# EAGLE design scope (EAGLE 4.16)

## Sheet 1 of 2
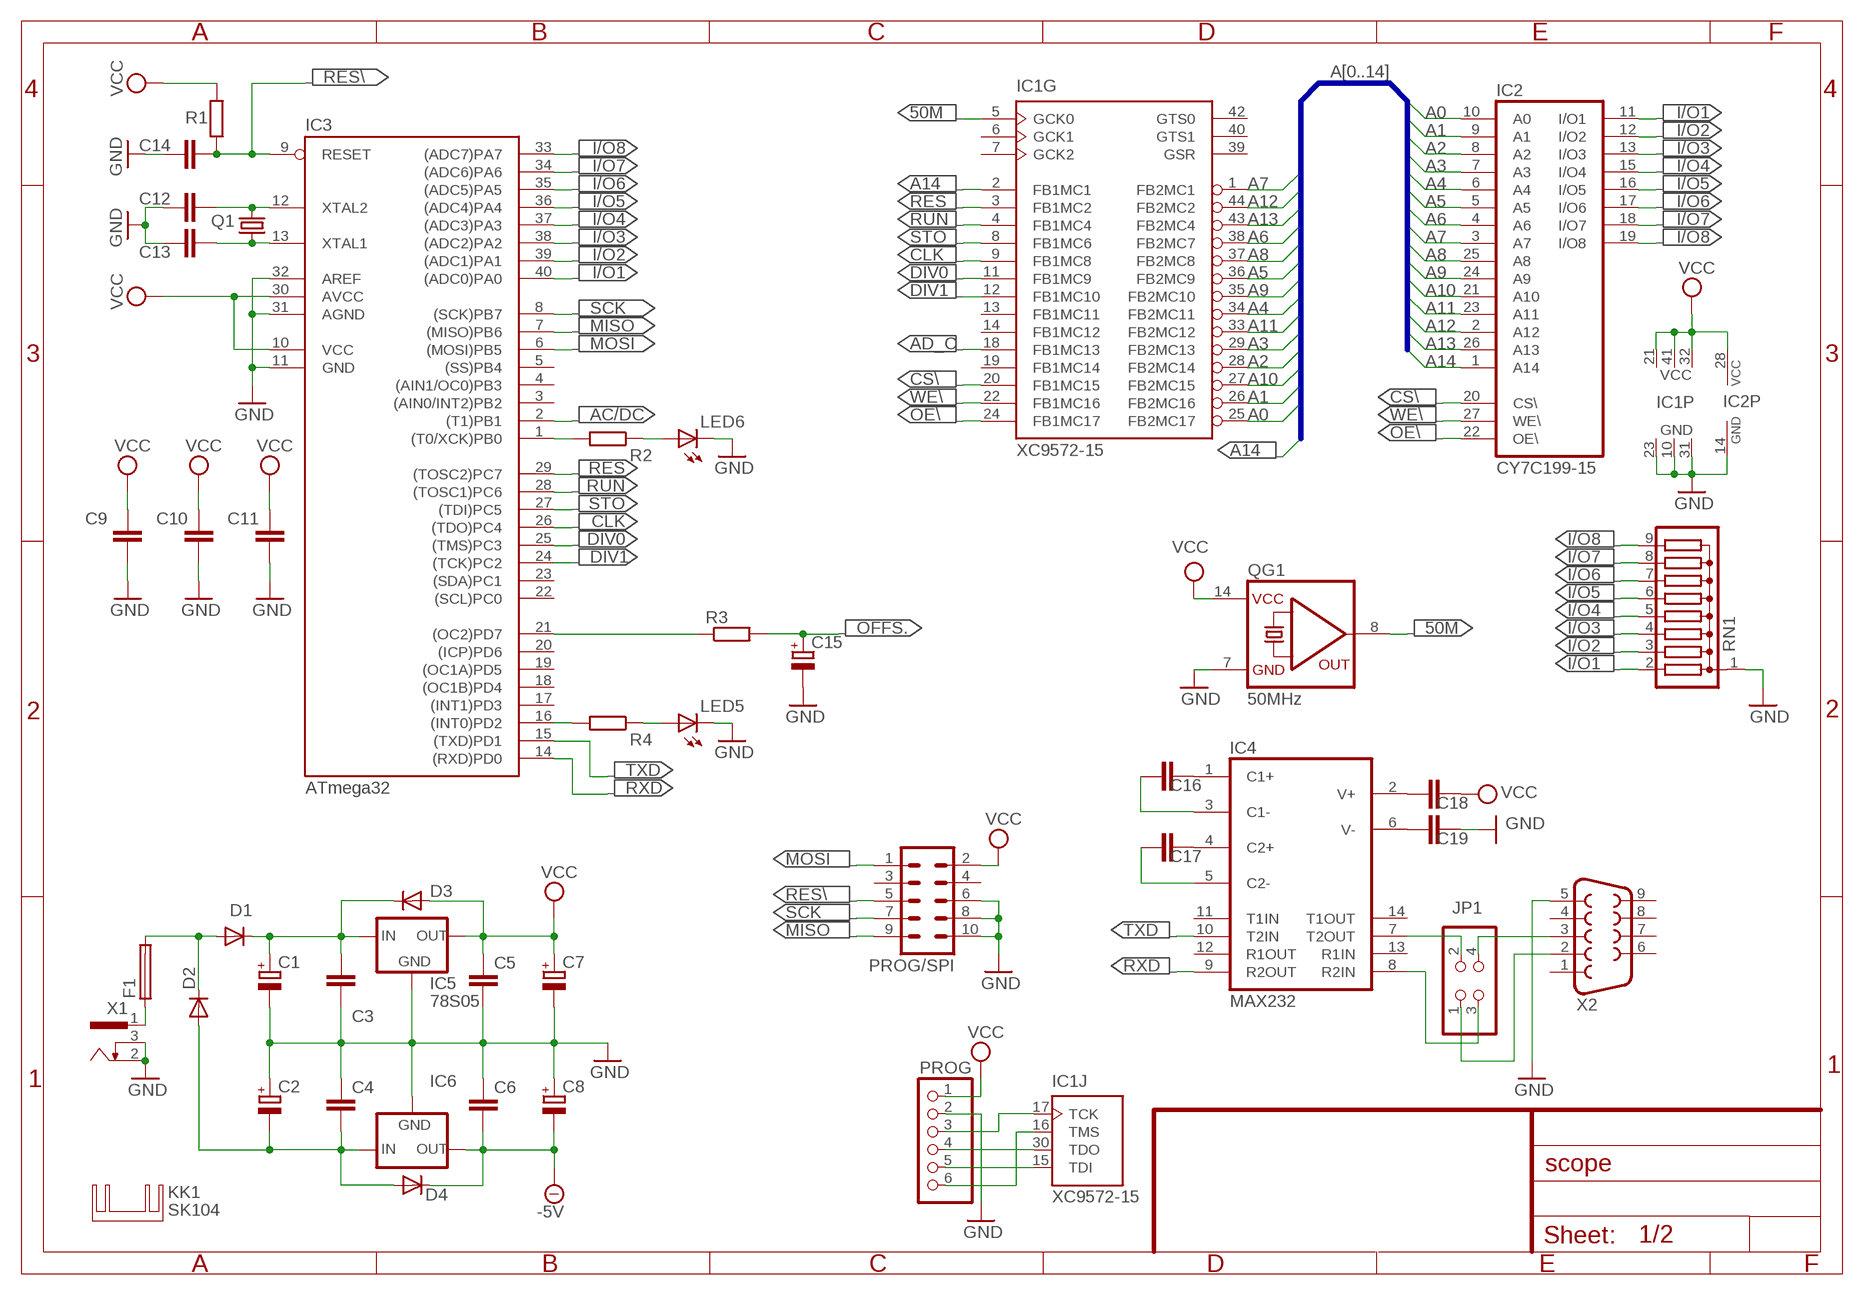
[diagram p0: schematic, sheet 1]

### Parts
C1  CPOL-EUE5-13  [E5-13]
C2  CPOL-EUE5-10.5  [E5-10,5]
C3  C-EU050-024X044  [C050-024X044]
C4  C-EU050-024X044  [C050-024X044]
C5  C-EU050-024X044  [C050-024X044]
C6  C-EU050-024X044  [C050-024X044]
C7  CPOL-EUE3.5-8  [E3,5-8]
C8  CPOL-EUE3.5-8  [E3,5-8]
C9  C-EU025-025X050  [C025-025X050]
C10  C-EU025-025X050  [C025-025X050]
C11  C-EU025-025X050  [C025-025X050]
C12  C-EU025-025X050  [C025-025X050]
C13  C-EU025-025X050  [C025-025X050]
C14  C-EU025-025X050  [C025-025X050]
C15  CPOL-EUE2-5  [E2-5]
C16  C-EU050-024X044  [C050-024X044]
C17  C-EU050-024X044  [C050-024X044]
C18  C-EU050-024X044  [C050-024X044]
C19  C-EU050-024X044  [C050-024X044]
D1  1N4004  [DO41-10]
D2  1N4004  [DO41-10]
D3  1N4004  [DO41-10]
D4  1N4004  [DO41-10]
F1  PICOFUSE  [PICOFUSE]
IC1  XC9572-15  XC9536-44  [PLCC-S44]
IC2  CY7C199-15  MB84256PSK  [DIL28-3]
IC3  ATmega32  MEGA32-P  [DIL40]
IC4  MAX232  [DIL16]
IC5  78S05  78XXS  [78XXS]
IC6  79XXS  [79XXS]
JP1  PINHD-2X2  [2X02]
KK1  SK104  [SK104]
LED5  LED3MM  [LED3MM]
LED6  LED3MM  [LED3MM]
PROG  PINHD-1X6  [1X06]
PROG/SPI  ML10  [ML10]
Q1  CRYSTALHC49U-V  [HC49U-V]
QG1  50MHz  QG5860  [DIL14S]
R1  R-EU_0207/10  [0207/10]
R2  R-EU_0207/10  [0207/10]
R3  R-EU_0207/10  [0207/10]
R4  R-EU_0207/10  [0207/10]
RN1  G08R  [SIL9]
X1  SCD-014A  [SCD-014-A]
X2  F09HP  [F09HP]

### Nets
50M: IC1.5(G:GCK0) QG1.8(OUT)
-5V: C6.2 C8.- D4.C IC6.OUT ; also sheet 2
A0: IC1.25(G:FB2MC17) IC2.10(A0)
A1: IC1.26(G:FB2MC16) IC2.9(A1)
A2: IC1.28(G:FB2MC14) IC2.8(A2)
A3: IC1.29(G:FB2MC13) IC2.7(A3)
A4: IC1.34(G:FB2MC11) IC2.6(A4)
A5: IC1.36(G:FB2MC9) IC2.5(A5)
A6: IC1.38(G:FB2MC7) IC2.4(A6)
A7: IC1.1(G:FB2MC1) IC2.3(A7)
A8: IC1.37(G:FB2MC8) IC2.25(A8)
A9: IC1.35(G:FB2MC10) IC2.24(A9)
A10: IC1.27(G:FB2MC15) IC2.21(A10)
A11: IC1.33(G:FB2MC12) IC2.23(A11)
A12: IC1.44(G:FB2MC2) IC2.2(A12)
A13: IC1.43(G:FB2MC4) IC2.26(A13)
A14: IC1.2(G:FB1MC1) IC2.1(A14)
AC/DC: IC3.2((T1)PB1) ; also sheet 2
AD_C: IC1.18(G:FB1MC13) ; also sheet 2
CLK: IC1.9(G:FB1MC8) IC3.26((TDO)PC4)
CS\: IC1.20(G:FB1MC15) IC2.20(CS\)
DIV0: IC1.11(G:FB1MC9) IC3.25((TMS)PC3)
DIV1: IC1.12(G:FB1MC10) IC3.24((TCK)PC2)
GND: C1.- C2.+ C3.2 C4.1 C5.2 C6.1 C7.- C8.+ C9.1 C10.1 C11.1 C12.1 C13.1 C14.1 C15.- C19.2 IC1.10(P:GND) IC1.23(P:GND) IC1.31(P:GND) IC2.14(GND) IC3.11(GND) IC3.31(AGND) IC3.32(AREF) IC5.GND IC6.GND LED5.K(C) LED6.K(C) PROG.2 PROG/SPI.6 PROG/SPI.8 PROG/SPI.10 QG1.7(GND) RN1.1 X1.2 X1.3 X2.5 ; also sheet 2
I/O1: IC2.11(I/O1) IC3.40((ADC0)PA0) RN1.2 ; also sheet 2
I/O2: IC2.12(I/O2) IC3.39((ADC1)PA1) RN1.3 ; also sheet 2
I/O3: IC2.13(I/O3) IC3.38((ADC2)PA2) RN1.4 ; also sheet 2
I/O4: IC2.15(I/O4) IC3.37((ADC3)PA3) RN1.5 ; also sheet 2
I/O5: IC2.16(I/O5) IC3.36((ADC4)PA4) RN1.6 ; also sheet 2
I/O6: IC2.17(I/O6) IC3.35((ADC5)PA5) RN1.7 ; also sheet 2
I/O7: IC2.18(I/O7) IC3.34((ADC6)PA6) RN1.8 ; also sheet 2
I/O8: IC2.19(I/O8) IC3.33((ADC7)PA7) RN1.9 ; also sheet 2
MISO: IC3.7((MISO)PB6) PROG/SPI.9
MOSI: IC3.6((MOSI)PB5) PROG/SPI.1
N$1: D1.A D2.C F1.2
N$2: F1.1 X1.1
N$3: C12.2 IC3.12(XTAL2) Q1.2
N$4: IC3.1((T0/XCK)PB0) R2.2
N$5: C13.2 IC3.13(XTAL1) Q1.1
N$6: LED6.A R2.1
N$7: C2.- C4.2 D2.A D4.A IC6.IN
N$15: IC1.16(J:TMS) PROG.6
N$16: IC1.15(J:TDI) PROG.5
N$17: IC1.30(J:TDO) PROG.4
N$18: IC1.17(J:TCK) PROG.3
N$25: IC3.21((OC2)PD7) R3.1
N$30: IC3.16((INT0)PD2) R4.2
N$31: LED5.A R4.1
N$40: JP1.1 X2.2
N$49: JP1.4 X2.3
N$50: IC4.8(R2IN) JP1.3
N$51: IC4.7(T2OUT) JP1.2
N$52: C17.2 IC4.4(C2+)
N$53: C17.1 IC4.5(C2-)
N$56: C16.1 IC4.3(C1-)
N$57: C16.2 IC4.1(C1+)
N$58: C18.1 IC4.2(V+)
N$59: C19.1 IC4.6(V-)
N$250: C1.+ C3.1 D1.C D3.C IC5.IN
OE\: IC1.24(G:FB1MC17) IC2.22(OE\)
OFFS.: C15.+ R3.2 ; also sheet 2
RES: IC1.3(G:FB1MC2) IC3.29((TOSC2)PC7)
RES\: C14.2 IC3.9(RESET) PROG/SPI.5 R1.1
RUN: IC1.4(G:FB1MC4) IC3.28((TOSC1)PC6)
RXD: IC3.14((RXD)PD0) IC4.9(R2OUT)
SCK: IC3.8((SCK)PB7) PROG/SPI.7
STO: IC1.8(G:FB1MC6) IC3.27((TDI)PC5)
TXD: IC3.15((TXD)PD1) IC4.10(T2IN)
VCC: C5.1 C7.+ C9.2 C10.2 C11.2 C18.2 D3.A IC1.21(P:VCC) IC1.32(P:VCC) IC1.41(P:VCC) IC2.28(VCC) IC3.10(VCC) IC3.30(AVCC) IC5.OUT PROG.1 PROG/SPI.2 QG1.14(VCC) R1.2 ; also sheet 2
WE\: IC1.22(G:FB1MC16) IC2.27(WE\) ; also sheet 2
Unconnected: IC1.6(G:GCK1) IC1.7(G:GCK2) IC1.13(G:FB1MC11) IC1.14(G:FB1MC12) IC1.19(G:FB1MC14) IC1.39(G:GSR) IC1.40(G:GTS1) IC1.42(G:GTS0) IC3.3((AIN0/INT2)PB2) IC3.4((AIN1/OC0)PB3) IC3.5((SS)PB4) IC3.17((INT1)PD3) IC3.18((OC1B)PD4) IC3.19((OC1A)PD5) IC3.20((ICP)PD6) IC3.22((SCL)PC0) IC3.23((SDA)PC1) IC4.11(T1IN) IC4.12(R1OUT) IC4.13(R1IN) IC4.14(T1OUT) PROG/SPI.3 PROG/SPI.4 X2.1 X2.4 X2.6 X2.7 X2.8 X2.9

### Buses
A[0..14]

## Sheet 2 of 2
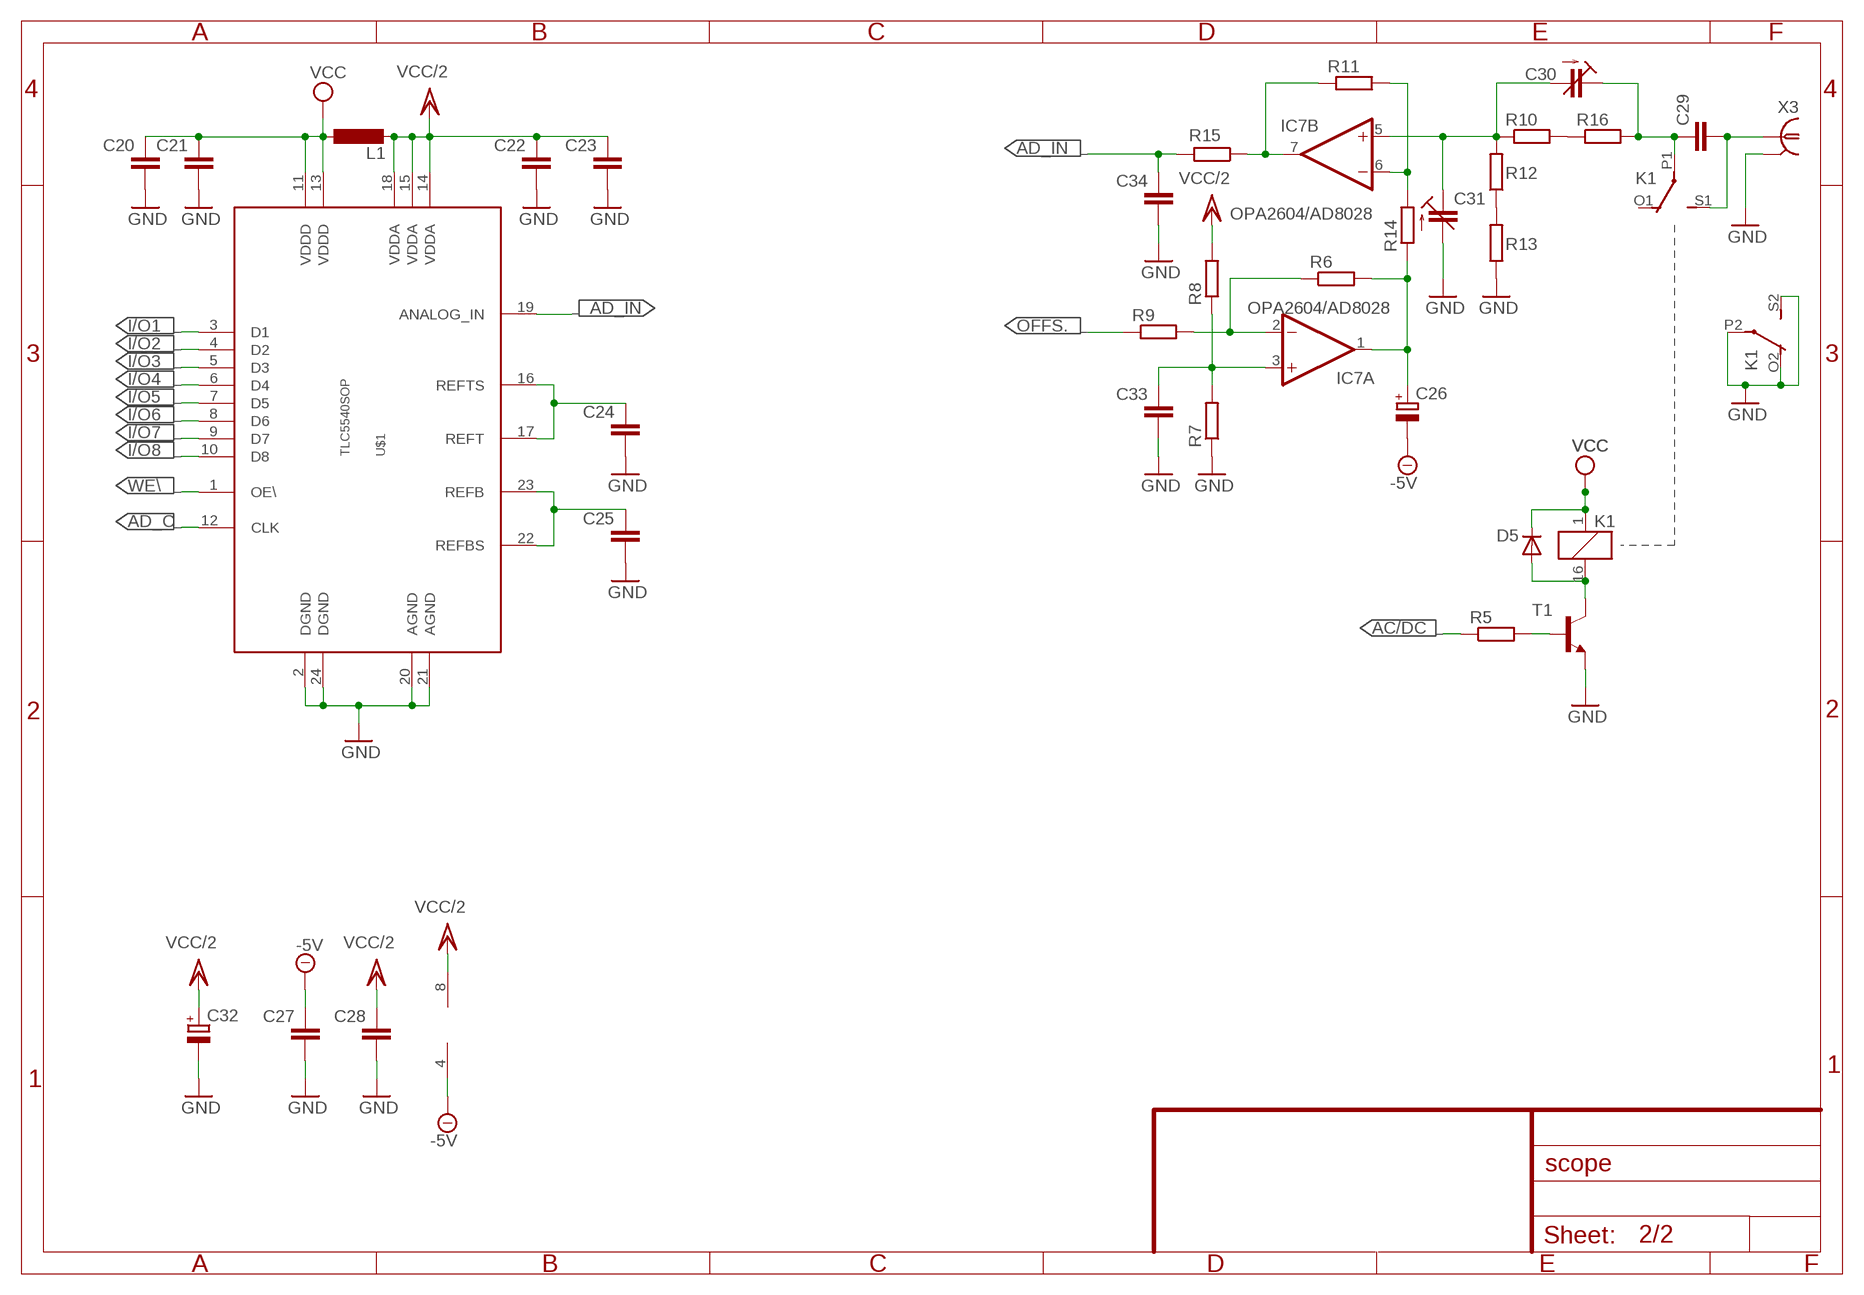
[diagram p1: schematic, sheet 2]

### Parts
C20  C-EU025-025X050  [C025-025X050]
C21  C-EU025-025X050  [C025-025X050]
C22  C-EU025-025X050  [C025-025X050]
C23  C-EU025-025X050  [C025-025X050]
C24  C-EU025-025X050  [C025-025X050]
C25  C-EU025-025X050  [C025-025X050]
C26  CPOL-EUE2.5-6  [E2,5-6]
C27  C-EU025-025X050  [C025-025X050]
C28  C-EU025-025X050  [C025-025X050]
C29  C-EU025-024X044  [C025-024X044]
C30  C-TRIMM808  [CTRIM808-BC]
C31  C-TRIMM808  [CTRIM808-BC]
C32  CPOL-EUE2.5-6  [E2,5-6]
C33  C-EU025-025X050  [C025-025X050]
C34  C-EU025-025X050  [C025-025X050]
D5  1N4148  [DO35-10]
IC7  OPA2604/AD8028  TL082P  [DIL08]
K1  351  [351]
L1  L-EU0204/7  [0204/7]
R5  R-EU_0207/10  [0207/10]
R6  R-EU_0207/10  [0207/10]
R7  R-EU_0207/10  [0207/10]
R8  R-EU_0207/10  [0207/10]
R9  R-EU_0207/10  [0207/10]
R10  R-EU_0207/10  [0207/10]
R11  R-EU_0207/10  [0207/10]
R12  R-EU_0207/10  [0207/10]
R13  R-EU_0207/10  [0207/10]
R14  R-EU_0207/10  [0207/10]
R15  R-EU_0207/10  [0207/10]
R16  R-EU_0207/10  [0207/10]
T1  BC547  [TO92]
U$1  TLC5540SOP  [SOP24]
X3  1-227161-0  [AMP_227161]

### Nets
-5V: C26.- C27.2 IC7.4(P:V-) ; also sheet 1
AC/DC: R5.1 ; also sheet 1
AD_C: U$1.12(CLK) ; also sheet 1
AD_IN: C34.2 R15.2 U$1.19(ANALOG_IN)
GND: C20.1 C21.1 C22.1 C23.1 C24.1 C25.1 C27.1 C28.1 C31.2(A) C32.- C33.1 C34.1 K1.O2(3:O) K1.P2(3:P) K1.S2(3:S) R7.1 R13.1 T1.1(E) U$1.2(DGND) U$1.20(AGND) U$1.21(AGND) U$1.24(DGND) X3.2(GND) ; also sheet 1
I/O1: U$1.3(D1) ; also sheet 1
I/O2: U$1.4(D2) ; also sheet 1
I/O3: U$1.5(D3) ; also sheet 1
I/O4: U$1.6(D4) ; also sheet 1
I/O5: U$1.7(D5) ; also sheet 1
I/O6: U$1.8(D6) ; also sheet 1
I/O7: U$1.9(D7) ; also sheet 1
I/O8: U$1.10(D8) ; also sheet 1
N$10: C29.2 K1.S1(2:S) X3.1
N$19: C26.+ IC7.1(A:OUT) R6.2 R14.1
N$20: C29.1 C30.1(E) K1.P1(2:P) R16.2
N$21: R5.2 T1.2(B)
N$22: C24.2 U$1.16(REFTS) U$1.17(REFT)
N$23: C25.2 U$1.22(REFBS) U$1.23(REFB)
N$24: D5.A K1.16 T1.3(C)
N$26: C33.2 IC7.3(A:+IN) R7.2 R8.1
N$27: IC7.7(B:OUT) R11.1 R15.1
N$28: IC7.6(B:-IN) R11.2 R14.2
N$29: IC7.2(A:-IN) R6.1 R9.2
N$32: R12.1 R13.2
N$33: C30.2(A) C31.1(E) IC7.5(B:+IN) R10.1 R12.2
N$34: R10.2 R16.1
OFFS.: R9.1 ; also sheet 1
VCC: C20.2 C21.2 D5.C K1.1 L1.1 U$1.11(VDDD) U$1.13(VDDD) ; also sheet 1
VCC/2: C22.2 C23.2 C28.2 C32.+ IC7.8(P:V+) L1.2 R8.2 U$1.14(VDDA) U$1.15(VDDA) U$1.18(VDDA)
WE\: U$1.1(OE\) ; also sheet 1
Unconnected: K1.O1(2:O)

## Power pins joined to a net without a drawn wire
GND: IC4.15(GND)
VCC: IC4.16(VCC)

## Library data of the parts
C1 C2 C7 C8 C15 C26 C32 = rcl:CPOL-EU: POLARIZED CAPACITOR, European symbol
C3-C6 C9-C14 C16-C25 C27-C29 C33 C34 = rcl:C-EU: CAPACITOR, European symbol
C30 C31 = rcl:C-TRIMM: Trimm capacitor
D1-D4 = diode:1N4004: DIODE
D5 = diode:1N4148: DIODE
F1 = fuse:PICOFUSE: PICOFUSE
IC1 = XILINX:XC9536-44
IC2 = micro-fujitsu:MB84256PSK: MICROCONTROLLER/MEMORY DEVICE
IC3 = atmel:MEGA32-P: MICROCONTROLLER 32 Kbytes FLASH 2 Kbytes SRAM 1 Kbytes EEPROM USART 8-channel 10 bit ADC Source: www.atmel.com .. doc2503.pdf
IC4 = maxim:MAX232: RS232 TRANSEIVER
IC5 = v-reg:78XXS: VOLTAGE REGULATOR
IC6 = v-reg:79XXS: VOLTAGE REGULATOR
IC7 = linear:TL082: OP AMP
JP1 = pinhead:PINHD-2X2: PIN HEADER
K1 = relay:351: RELAY 2 x switch, Omron
KK1 = heatsink:SK104: HEATSINK
L1 = rcl:L-EU: INDUCTOR, European symbol
LED5 LED6 = led:LED: LED
PROG = pinhead:PINHD-1X6: PIN HEADER
PROG/SPI = con-harting-ml:ML10: HARTING
Q1 = crystal:CRYSTAL: CRYSTAL
QG1 = crystal:QG5860: CRYSTAL RESONATOR
R1-R16 = rcl:R-EU_: RESISTOR, European symbol
RN1 = resistor-sil:G08R: SIL RESISTOR
T1 = transistor-npn:BC547*: NPN Transistor
U$1 = TLC5540:TLC5540SOP
X1 = con-shiua-chyuan:SCD-014A: Power Jack 2.5mm
X2 = con-subd:F09: SUB-D
X3 = con-coax:?227161*: JACK, RIGHT ANGLE, 50 OHM, PCB, BNC

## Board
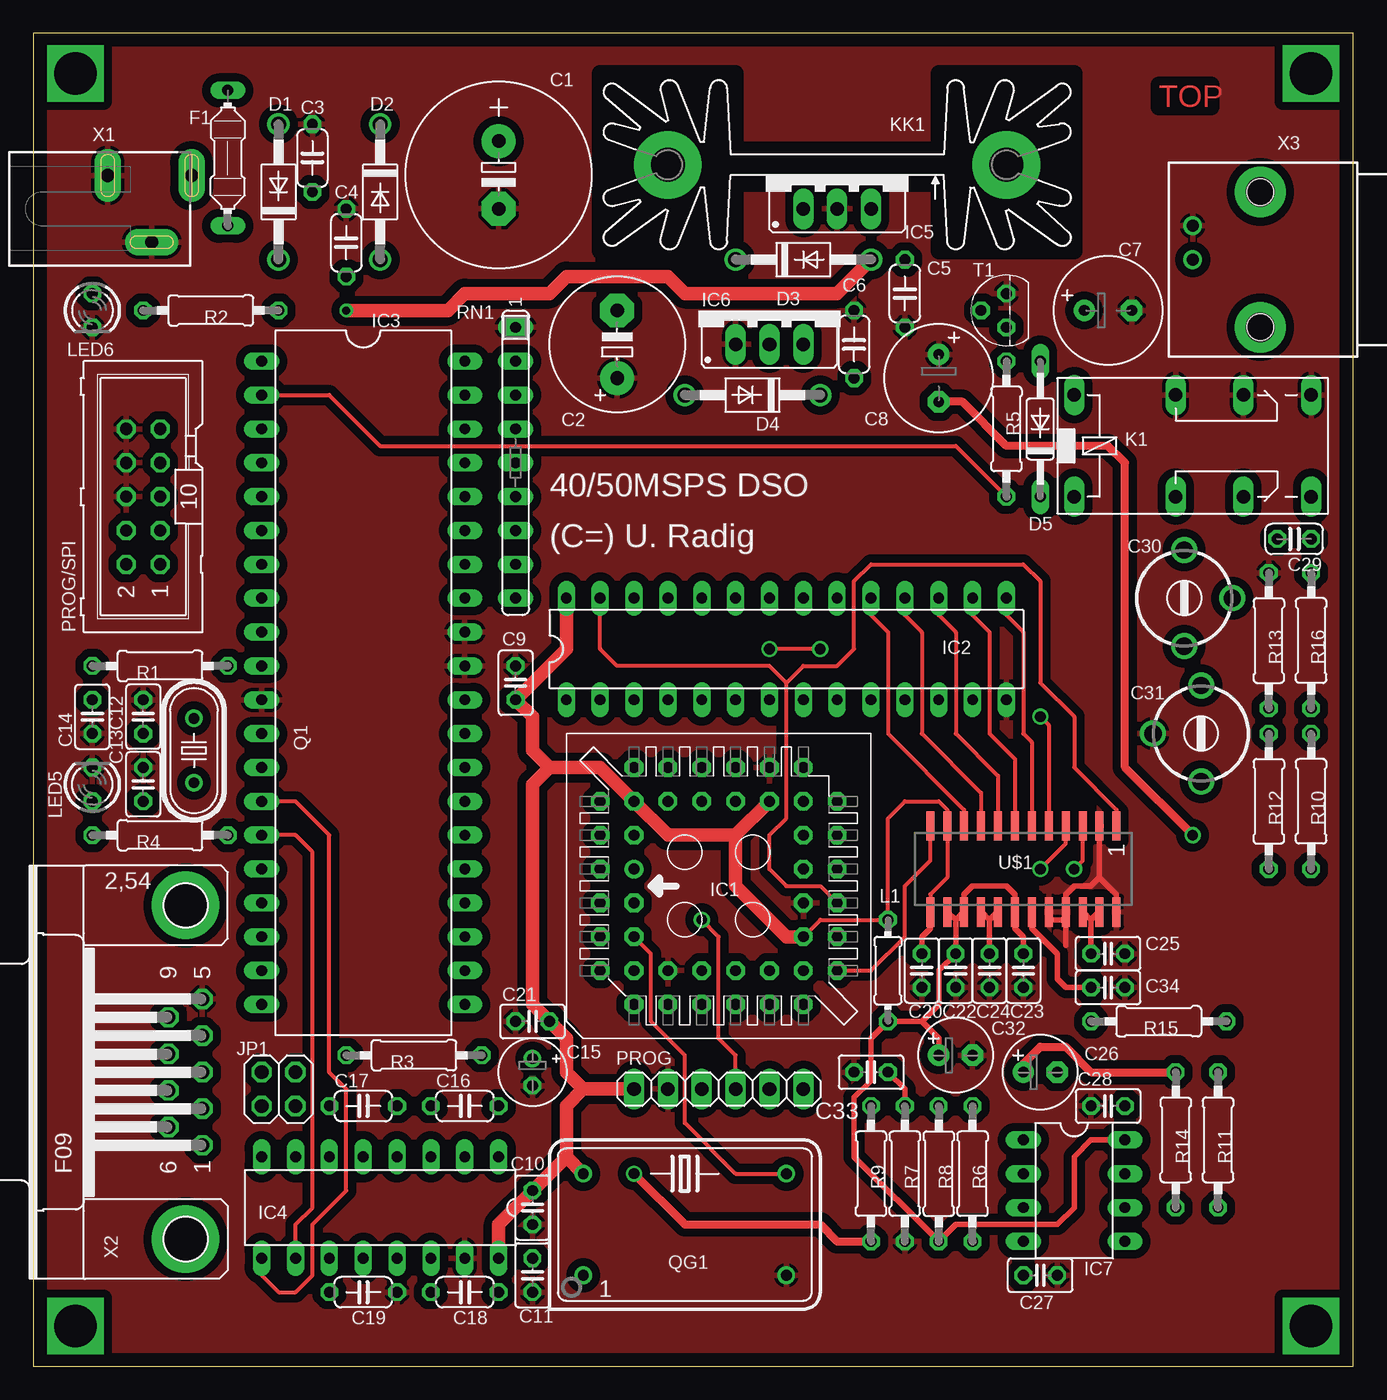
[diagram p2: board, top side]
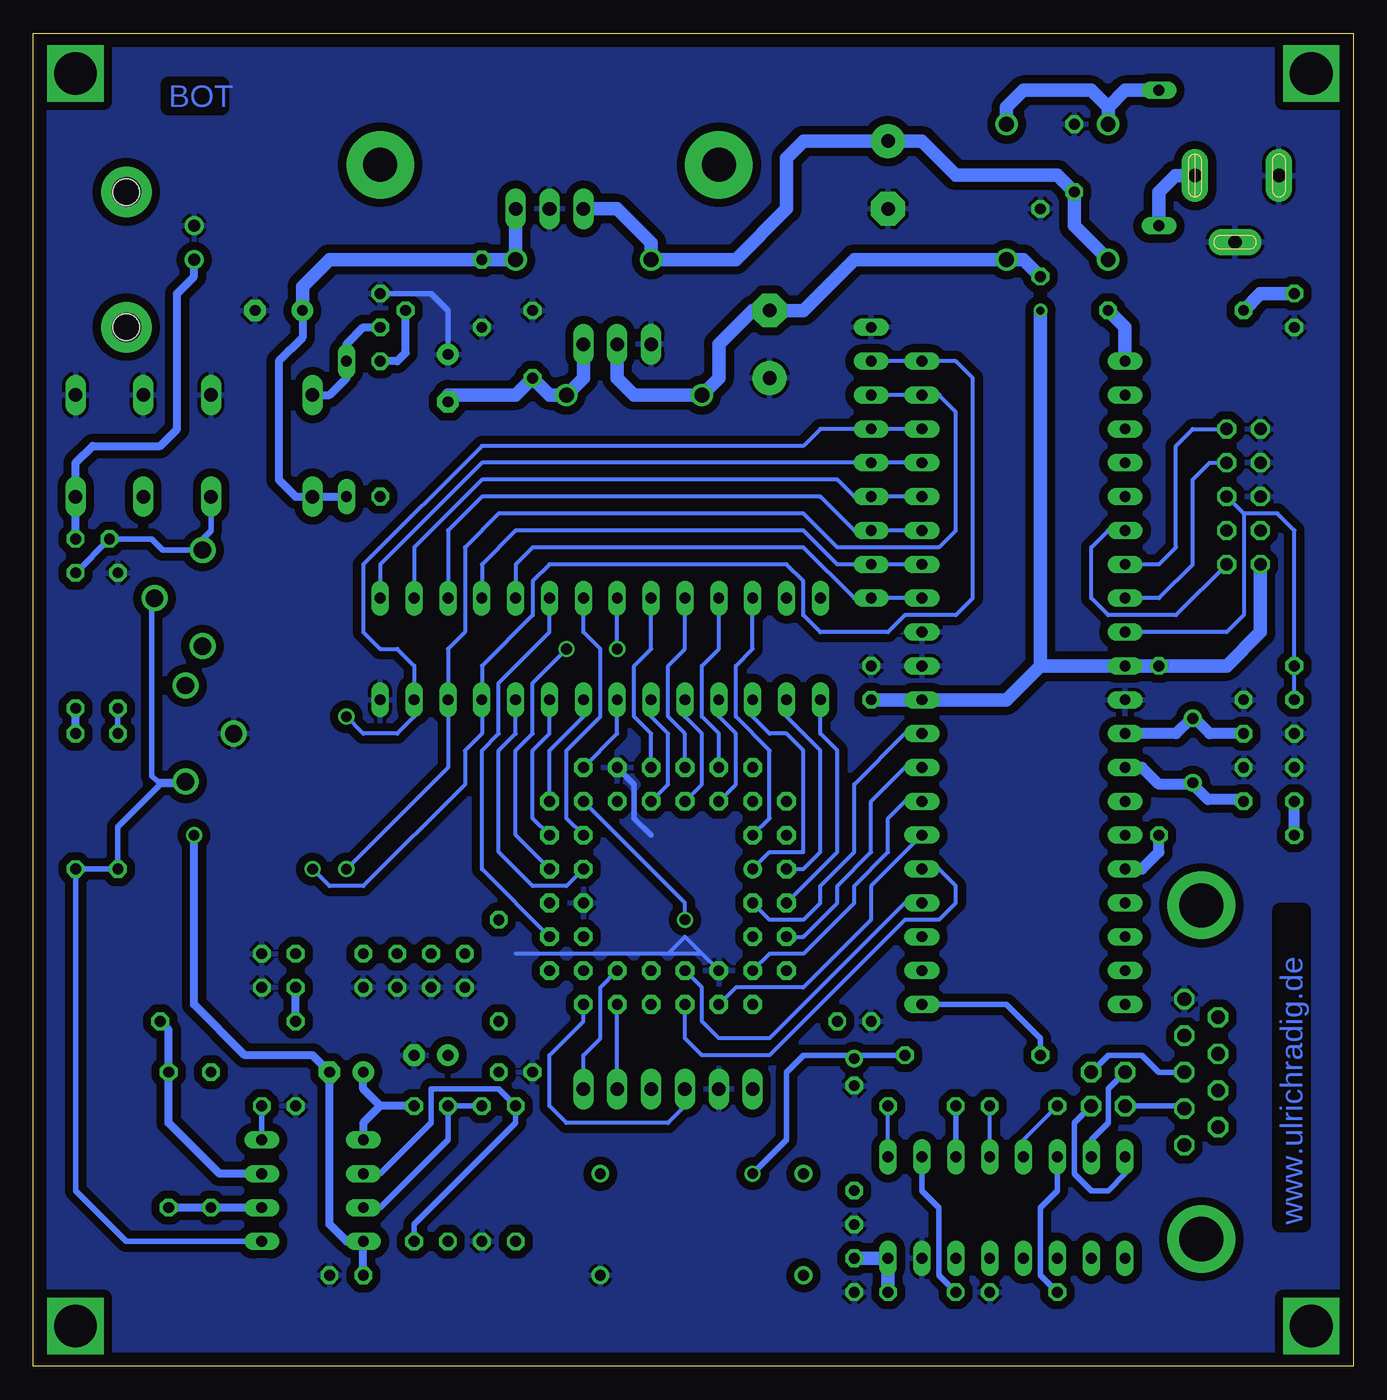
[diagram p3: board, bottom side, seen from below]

Size 99.04 x 100 mm. Coordinates in mm from the lower left corner, seen from the top.
Outline: 99.04,100 0,100 0,0 99.04,0 99.04,100
Copper layers (1*16): Top 0.035mm / dielectric 1.5mm / Bottom 0.035mm
Design rules "default": minimum track width 10mil, minimum drill 24mil, track to track 8mil, track to pad 8mil, pad to pad 8mil, via to via 8mil, smd to smd 8mil, copper to edge 40mil, drill to drill 8mil, minimum pad ring 10mil, minimum via ring 8mil, stop-mask expansion 4mil, vias tented up to drill 0mil, thermal gap 10mil

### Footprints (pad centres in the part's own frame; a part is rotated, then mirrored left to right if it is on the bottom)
E5-13 = drill 1.016 pad 2.54 round: + -2.54,0 | drill 1.016 pad 2.54 octagon: - 2.54,0
E5-10,5 = drill 1.016 pad 2.54 round: + -2.54,0 | drill 1.016 pad 2.54 octagon: - 2.54,0
C050-024X044 = drill 0.813 octagon: 1 -2.54,0; 2 2.54,0
E3,5-8 = drill 0.813 pad 1.6 round: + -1.778,0 | drill 0.813 pad 1.6 octagon: - 1.778,0
C025-025X050 = drill 0.813 octagon: 1 -1.27,0; 2 1.27,0
E2-5 = drill 0.813 pad 1.27 round: + -1.016,0 | drill 0.813 pad 1.27 octagon: - 1.016,0
E2,5-6 = drill 0.813 pad 1.6 round: + -1.27,0 | drill 0.813 pad 1.6 octagon: - 1.27,0
C025-024X044 = drill 0.813 octagon: 1 -1.27,0; 2 1.27,0
CTRIM808-BC = drill 1.3 round: 1 -3.607,0; 2 0,3.607; 3 3.607,0
DO41-10 = drill 1.118 round: A 5.08,0; C -5.08,0
DO35-10 = drill 0.813 long: A 5.08,0; C -5.08,0
PICOFUSE = drill 0.813 long: 1 -5.08,0; 2 5.08,0
PLCC-S44 = drill 0.813 pad 1.397 round: 1 1.27,6.35 | drill 0.813 pad 1.397 octagon: 2 -1.27,8.89; 3 -1.27,6.35; 4 -3.81,8.89; 5 -3.81,6.35; 6 -6.35,8.89; 7 -8.89,6.35; 8 -6.35,6.35; 9 -8.89,3.81; 10 -6.35,3.81; 11 -8.89,1.27; 12 -6.35,1.27; 13 -8.89,-1.27; 14 -6.35,-1.27; 15 -8.89,-3.81; 16 -6.35,-3.81; 17 -8.89,-6.35; 18 -6.35,-8.89; 19 -6.35,-6.35; 20 -3.81,-8.89; 21 -3.81,-6.35; 22 -1.27,-8.89; 23 -1.27,-6.35; 24 1.27,-8.89; 25 1.27,-6.35; 26 3.81,-8.89; 27 3.81,-6.35; 28 6.35,-8.89; 29 8.89,-6.35; 30 6.35,-6.35; 31 8.89,-3.81; 32 6.35,-3.81; 33 8.89,-1.27; 34 6.35,-1.27; 35 8.89,1.27; 36 6.35,1.27; 37 8.89,3.81; 38 6.35,3.81; 39 8.89,6.35; 40 6.35,8.89; 41 6.35,6.35; 42 3.81,8.89; 43 3.81,6.35; 44 1.27,8.89
DIL28-3 = drill 0.813 long: 1 -16.51,-3.81; 2 -13.97,-3.81; 3 -11.43,-3.81; 4 -8.89,-3.81; 5 -6.35,-3.81; 6 -3.81,-3.81; 7 -1.27,-3.81; 8 1.27,-3.81; 9 3.81,-3.81; 10 6.35,-3.81; 11 8.89,-3.81; 12 11.43,-3.81; 13 13.97,-3.81; 14 16.51,-3.81; 15 16.51,3.81; 16 13.97,3.81; 17 11.43,3.81; 18 8.89,3.81; 19 6.35,3.81; 20 3.81,3.81; 21 1.27,3.81; 22 -1.27,3.81; 23 -3.81,3.81; 24 -6.35,3.81; 25 -8.89,3.81; 26 -11.43,3.81; 27 -13.97,3.81; 28 -16.51,3.81
DIL40 = drill 0.813 long: 1 -24.13,-7.62; 2 -21.59,-7.62; 3 -19.05,-7.62; 4 -16.51,-7.62; 5 -13.97,-7.62; 6 -11.43,-7.62; 7 -8.89,-7.62; 8 -6.35,-7.62; 9 -3.81,-7.62; 10 -1.27,-7.62; 11 1.27,-7.62; 12 3.81,-7.62; 13 6.35,-7.62; 14 8.89,-7.62; 15 11.43,-7.62; 16 13.97,-7.62; 17 16.51,-7.62; 18 19.05,-7.62; 19 21.59,-7.62; 20 24.13,-7.62; 21 24.13,7.62; 22 21.59,7.62; 23 19.05,7.62; 24 16.51,7.62; 25 13.97,7.62; 26 11.43,7.62; 27 8.89,7.62; 28 6.35,7.62; 29 3.81,7.62; 30 1.27,7.62; 31 -1.27,7.62; 32 -3.81,7.62; 33 -6.35,7.62; 34 -8.89,7.62; 35 -11.43,7.62; 36 -13.97,7.62; 37 -16.51,7.62; 38 -19.05,7.62; 39 -21.59,7.62; 40 -24.13,7.62
DIL16 = drill 0.813 long: 1 -8.89,-3.81; 2 -6.35,-3.81; 3 -3.81,-3.81; 4 -1.27,-3.81; 5 1.27,-3.81; 6 3.81,-3.81; 7 6.35,-3.81; 8 8.89,-3.81; 9 8.89,3.81; 10 6.35,3.81; 11 3.81,3.81; 12 1.27,3.81; 13 -1.27,3.81; 14 -3.81,3.81; 15 -6.35,3.81; 16 -8.89,3.81
78XXS = drill 1.016 long: GND 0,-2.54; IN -2.54,-2.54; OUT 2.54,-2.54
79XXS = drill 1.016 long: GND -2.54,-2.54; IN 0,-2.54; OUT 2.54,-2.54
DIL08 = drill 0.813 long: 1 -3.81,-3.81; 2 -1.27,-3.81; 3 1.27,-3.81; 4 3.81,-3.81; 5 3.81,3.81; 6 1.27,3.81; 7 -1.27,3.81; 8 -3.81,3.81
2X02 = drill 1.016 octagon: 1 -1.27,-1.27; 2 -1.27,1.27; 3 1.27,-1.27; 4 1.27,1.27
351 = drill 1.016 long: 1 -3.81,-3.81; 16 -3.81,3.81; O1 8.89,-3.81; O2 8.89,3.81; P1 3.81,-3.81; P2 3.81,3.81; S1 13.97,-3.81; S2 13.97,3.81
SK104 = drill 2.54 pad 5.08 round: A2,5 -12.7,-0.762; B2,5 12.7,-0.762
0204/7 = drill 0.813 octagon: 1 -3.81,0; 2 3.81,0
LED3MM = drill 0.813 octagon: A -1.27,0; K 1.27,0
1X06 = drill 1.016 long: 1 -6.35,0; 2 -3.81,0; 3 -1.27,0; 4 1.27,0; 5 3.81,0; 6 6.35,0
ML10 = drill 0.914 octagon: 1 -5.08,-1.27; 2 -5.08,1.27; 3 -2.54,-1.27; 4 -2.54,1.27; 5 0,-1.27; 6 0,1.27; 7 2.54,-1.27; 8 2.54,1.27; 9 5.08,-1.27; 10 5.08,1.27
HC49U-V = drill 0.813 round: 1 -2.413,0; 2 2.413,0
DIL14S = drill 0.813 round: 1 -7.62,-3.81; 7 7.62,-3.81; 8 7.62,3.81; 14 -7.62,3.81
0207/10 = drill 0.813 octagon: 1 -5.08,0; 2 5.08,0
SIL9 = drill 0.813 long: 1 -10.16,0; 2 -7.62,0; 3 -5.08,0; 4 -2.54,0; 5 0,0; 6 2.54,0; 7 5.08,0; 8 7.62,0; 9 10.16,0
TO92 = drill 0.813 octagon: 1 1.27,0; 2 0,1.905; 3 -1.27,0
SOP24 = smd 2.2 x 0.6: 1 -4.5,6.985; 2 -4.5,5.715; 3 -4.5,4.445; 4 -4.5,3.175; 5 -4.5,1.905; 6 -4.5,0.635; 7 -4.5,-0.635; 8 -4.5,-1.905; 9 -4.5,-3.175; 10 -4.5,-4.445; 11 -4.5,-5.715; 12 -4.5,-6.985; 13 1.96,-6.985; 14 1.96,-5.715; 15 1.96,-4.445; 16 1.96,-3.175; 17 1.96,-1.905; 18 1.96,-0.635; 19 1.96,0.635; 20 1.96,1.905; 21 1.96,3.175; 22 1.96,4.445; 23 1.96,5.715; 24 1.96,6.985
SCD-014-A = drill 1 pad 2 long: 1 -2.5,13.8; 2 -2.5,7.5; 3 2.5,10.8
F09HP = drill 1.016 octagon: 1 -5.486,-1.27; 2 -2.743,-1.27; 3 0,-1.27; 4 2.743,-1.27; 5 5.486,-1.27; 6 -4.115,1.27; 7 -1.372,1.27; 8 1.372,1.27; 9 4.115,1.27 | drill 3.302 pad 5.08 round: G1 -12.522,0; G2 12.522,0
AMP_227161 = drill 0.9 pad 1.27 round: 1 0,-5.08; 2 -2.54,-5.08 | hole 2: -5.08,0; 5.08,0

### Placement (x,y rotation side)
C1  34.91,89.37 270 top
C2  43.8,76.67 90 top
C3  20.94,90.64 90 top
C4  23.48,84.29 270 top
C5  65.39,80.48 270 top
C6  61.58,76.67 270 top
C7  80.63,79.21 0 top
C8  67.93,74.13 270 top
C9  36.18,51.27 270 top
C10  37.45,11.9 90 top
C11  37.45,6.82 90 top
C12  8.24,48.73 270 top
C13  8.24,43.65 270 top
C14  4.43,48.73 90 top
C15  37.45,22.06 270 top
C16  32.37,19.52 0 top
C17  24.75,19.52 0 top
C18  32.37,5.55 0 top
C19  24.75,5.55 0 top
C20  66.66,29.68 90 top
C21  37.45,25.87 0 top
C22  69.2,29.68 90 top
C23  74.28,29.68 90 top
C24  71.74,29.68 90 top
C25  80.63,30.95 180 top
C26  75.55,22.06 0 top
C27  75.55,6.82 180 top
C28  80.63,19.52 0 top
C29  94.6,62.06 0 top
C30  86.34,57.62 270 top
C31  87.62,47.46 90 top
C32  69.2,23.33 0 top
C33  62.85,22.06 0 top
C34  80.63,28.41 180 top
D1  18.4,88.1 90 top
D2  26.02,88.1 270 top
D3  57.77,83.02 0 top
D4  53.96,72.86 180 top
D5  75.55,70.32 90 top
F1  14.59,90.64 90 top
IC1  51.42,36.03 90 top
IC2  56.5,53.81 0 top
IC3  24.75,51.27 270 top
IC4  26.02,11.9 180 top
IC5  60.31,89.37 0 top
IC6  55.23,79.21 0 top
IC7  78.09,13.17 270 top
JP1  18.4,20.79 0 top
K1  81.9,69.05 0 top
KK1  60.31,89.37 180 top
L1  64.12,29.68 270 top
LED5  4.43,43.65 90 top
LED6  4.43,79.21 270 top
PROG  51.42,20.79 0 top
PROG/SPI  8.24,65.24 90 top
Q1  12.05,46.19 90 top
QG1  48.88,10.63 0 top
R1  9.51,52.54 0 top
R2  13.32,79.21 0 top
R3  28.56,23.33 0 top
R4  9.51,39.84 0 top
R5  73.01,70.32 90 top
R6  70.47,14.44 90 top
R7  65.39,14.44 90 top
R8  67.93,14.44 270 top
R9  62.85,14.44 90 top
R10  95.87,42.38 90 top
R11  88.89,16.98 270 top
R12  92.7,42.38 270 top
R13  92.7,54.45 270 top
R14  85.71,16.98 270 top
R15  84.44,25.87 180 top
R16  95.87,54.45 90 top
RN1  36.18,67.78 270 top
T1  73.01,79.21 90 top
U$1  74.28,36.03 270 top
X1  -1.92,86.83 270 top
X2  11.41,22.06 90 top
X3  92.06,83.02 270 top

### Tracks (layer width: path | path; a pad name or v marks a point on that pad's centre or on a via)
50M
  Top 0.305: QG1.8 52.69,14.44 48.88,18.25 48.88,23.33 46.34,25.87 46.34,30.95 IC1.5
-5V  (via drill 0.8 pad 0.61)
  Top 0.61: C8.- 69.71,72.35 73.01,69.05 80.63,69.05 81.9,67.78 81.9,44.92 v86.98,39.84
  Bottom 0.61: C27.2 IC7.4 75.55,9.36 76.82,10.63 C26.- 78.09,23.33 83.17,23.33 86.98,27.14 v86.98,39.84
  Bottom 1.016: IC6.OUT 57.77,74.13 D4.C 60.31,72.86 C6.2 62.85,72.86 67.93,72.86 C8.-
A0
  Bottom 0.305: IC1.25 59.04,36.03 61.58,36.03 64.12,38.57 64.12,46.19 62.85,47.46 IC2.10
A1
  Bottom 0.305: IC1.26 61.58,41.11 61.58,46.19 60.31,47.46 IC2.9
A2
  Bottom 0.305: IC2.8 57.77,48.73 60.31,46.19 IC1.28
A3
  Bottom 0.305: IC1.29 55.23,47.46 IC2.7
A4
  Bottom 0.305: IC1.34 51.42,43.65 51.42,47.46 52.69,48.73 IC2.6
A5
  Bottom 0.305: IC1.36 48.88,43.65 48.88,47.46 50.15,48.73 IC2.5
A6
  Bottom 0.305: IC1.38 46.34,43.65 46.34,47.46 47.61,48.73 IC2.4
A7
  Bottom 0.305: IC1.1 43.8,38.57 | 43.8,38.57 42.53,38.57 | 43.8,38.57 41.26,38.57 41.26,46.19 42.53,47.46 43.8,47.46 45.07,48.73 IC2.3
A8
  Bottom 0.305: IC1.37 47.61,47.46 48.88,48.73 48.88,52.54 47.61,53.81 IC2.25
A9
  Bottom 0.305: IC1.35 50.15,47.46 51.42,48.73 51.42,52.54 50.15,53.81 IC2.24
A10
  Bottom 0.305: IC1.27 59.04,41.11 59.04,46.19 56.5,48.73 56.5,53.81 57.77,55.08 IC2.21
A11
  Bottom 0.305: IC1.33 52.69,47.46 53.96,48.73 53.96,52.54 52.69,53.81 IC2.23
A12
  Bottom 0.305: IC1.44 41.26,37.3 39.99,38.57 39.99,46.19 42.53,48.73 IC2.2
A13
  Bottom 0.305: IC1.43 43.8,41.11 43.8,46.19 46.34,48.73 46.34,52.54 45.07,53.81 IC2.26
A14
  Bottom 0.305: IC2.1 39.99,47.46 38.72,46.19 38.72,38.57 IC1.2
AC/DC
  Top 0.305: IC3.2 22.21,72.86 26.02,69.05 69.2,69.05 R5.1
AD_C
  Top 0.305: IC1.18 62.85,29.68 65.39,32.22 65.39,36.03 67.3,37.94 U$1.12
AD_IN
  Top 0.406: U$1.19 74.92,32.85 76.82,30.95 76.82,29.04 77.45,28.41 C34.2
  Bottom 0.61: R15.2 C34.2
CLK
  Bottom 0.305: IC1.9 46.34,28.41 41.26,28.41 36.18,33.49 36.18,36.03 IC3.26
CS\
  Bottom 0.305: IC2.20 60.31,55.08 64.12,51.27 64.12,47.46 65.39,46.19 65.39,37.3 IC1.20
DIV0
  Bottom 0.305: IC3.25 31.1,37.3 29.83,36.03 29.83,34.76 31.1,33.49 33.64,33.49 43.8,23.33 48.88,23.33 50.15,24.6 IC1.11
DIV1
  Bottom 0.305: IC3.24 33.64,34.76 43.8,24.6 47.61,24.6 48.88,25.87 48.88,28.41 IC1.12
GND
  Top 0.406: 80,36.66 U$1.2 | U$1.24 81.27,35.39 80,36.66 | 77.45,33.49 U$1.21 77.45,35.39 78.09,36.03 79.36,36.03 80,36.66 | U$1.20 76.19,33.49 77.45,33.49 | 77.45,33.49 77.45,31.58
  Bottom 0.305: 48.88,30.95 50.15,32.22 51.42,30.95 | IC1.10 48.88,30.95 | 48.88,30.95 62.85,30.95
  Bottom 0.406: IC1.31 53.96,43.65 53.96,41.11 52.69,39.84 | C8.+ 67.93,79.21 69.2,80.48 T1.1
  pour Bottom (isolate 0.61): 98.41,0.47 0.62,0.47 0.62,99.53 98.41,99.53
  pour Top (isolate 0.61): 0.62,99.53 98.41,99.53 98.41,0.47 0.62,0.47
I/O1  (via drill 0.8)
  Top 0.305: U$1.3 78.73,37.94 v78.09,37.3
  Bottom 0.305: IC3.40 RN1.2 IC3.40 | IC3.40 29.83,75.4 28.56,74.13 28.56,57.62 29.83,56.35 33.64,56.35 34.91,55.08 39.99,55.08 41.26,56.35 41.26,58.89 42.53,60.16 60.31,60.16 61.58,58.89 61.58,56.35 65.39,52.54 IC2.11 65.39,47.46 66.66,46.19 66.66,43.65 74.28,36.03 76.82,36.03 v78.09,37.3
I/O2  (via drill 0.8)
  Top 0.305: U$1.4 77.45,39.2 v75.55,37.3
  Bottom 0.305: 31.1,72.86 29.83,71.59 29.83,62.7 31.1,61.43 38.72,61.43 41.26,63.97 64.12,63.97 66.66,61.43 66.66,55.08 67.93,53.81 IC2.12 67.93,44.92 v75.55,37.3 | IC3.39 RN1.3 IC3.39
  Bottom 0.406: 31.1,72.86 IC3.39
I/O3  (via drill 0.8 pad 0.61)
  Top 0.305: U$1.5 76.19,48.09 v75.55,48.73
  Bottom 0.305: IC3.38 RN1.4 39.99,70.32 41.26,69.05 65.39,69.05 74.28,60.16 74.28,55.08 73.01,53.81 71.74,53.81 70.47,52.54 IC2.13 70.47,48.73 71.74,47.46 74.28,47.46 v75.55,48.73
I/O4
  Top 0.305: IC2.15 73.01,56.35 74.28,55.08 74.28,47.46 74.92,46.82 U$1.6
  Bottom 0.305: IC3.37 RN1.5 65.39,67.78 73.01,60.16 IC2.15
I/O5
  Top 0.305: IC2.16 70.47,56.35 71.74,55.08 71.74,47.46 73.65,45.55 U$1.7
  Bottom 0.305: IC3.36 RN1.6 37.45,65.24 38.72,66.51 65.39,66.51 70.47,61.43 IC2.16
I/O6
  Top 0.305: IC2.17 67.93,56.35 69.2,55.08 69.2,47.46 72.38,44.28 U$1.8
  Bottom 0.305: IC3.35 RN1.7 37.45,62.7 39.99,65.24 65.39,65.24 67.93,62.7 IC2.17
I/O7
  Top 0.305: IC2.18 65.39,56.35 66.66,55.08 66.66,47.46 71.11,43.02 U$1.9
  Bottom 0.305: IC3.34 RN1.8 38.72,60.16 41.26,62.7 62.85,62.7 65.39,60.16 IC2.18
I/O8
  Top 0.305: IC2.19 62.85,56.35 64.12,55.08 64.12,47.46 69.84,41.74 U$1.10
  Bottom 0.305: IC3.33 RN1.9 37.45,57.62 41.26,61.43 61.58,61.43 62.85,60.16 IC2.19
MISO
  Bottom 0.305: IC3.7 14.59,60.16 13.32,61.43 13.32,69.05 12.05,70.32 PROG/SPI.9
MOSI
  Bottom 0.305: PROG/SPI.1 13.32,56.35 18.4,56.35 19.67,57.62 19.67,61.43 18.4,62.7 IC3.6
N$1
  Bottom 1.016: F1.2 17.13,95.72 18.4,94.45 | 18.4,94.45 D1.A | 18.4,94.45 19.67,95.72 24.75,95.72 26.02,94.45 D2.C
N$2
  Bottom 1.016: X1.1 13.36,89.33 14.59,88.1 F1.1
N$3
  Bottom 0.813: C12.2 10.78,47.46 12.05,48.73 Q1.2 12.18,48.6 13.32,47.46 IC3.12
N$4
  Bottom 1.016: IC3.1 17.13,77.94 R2.2
N$5
  Bottom 0.406: C13.2 8.37,42.51
  Bottom 0.813: 8.37,42.51 10.91,42.51 12.05,43.65 14.59,43.65 15.86,44.92 IC3.13
  Bottom 1.016: 12.05,43.65 Q1.1
N$6
  Bottom 1.016: LED6.A 6.97,80.48 R2.1
N$7
  Bottom 1.016: IC6.IN 55.23,74.13 53.96,72.86 D4.A 47.61,74.13 47.61,76.67 45.07,79.21 C2.- 41.26,79.21 37.45,83.02 D2.A 24.75,83.02 C4.2
N$8  (via drill 2.2 pad 3.81)
  other vias: 92.06,88.1
N$9  (via drill 2.2 pad 3.81)
  other vias: 92.06,77.94
N$10
  Bottom 0.61: X3.1 86.98,81.75 88.25,80.48 88.25,70.32 89.52,69.05 94.6,69.05 95.87,67.78 K1.S1 C29.2
N$11  (via drill 3.2)
  other vias: 95.87,3.01
N$12  (via drill 3.2)
  other vias: 95.87,96.99
N$13  (via drill 3.2 pad 1.68)
  other vias: 3.16,96.99
N$14  (via drill 3.2 pad 1.68)
  other vias: 3.16,3.01
N$15
  Bottom 0.305: PROG.6 57.77,23.33 56.5,24.6 56.5,28.41 IC1.16
N$16
  Bottom 0.305: PROG.5 IC1.15
N$17  (via drill 0.8)
  Top 0.305: v50.15,33.49 51.42,32.22 51.42,24.6 52.69,23.33 PROG.4
  Bottom 0.305: v50.15,33.49 50.15,34.76 IC1.30
N$18
  Bottom 0.305: PROG.3 50.15,19.52 51.42,18.25 59.04,18.25 60.31,19.52 60.31,23.33 57.77,25.87 IC1.17
N$19
  Top 0.61: C26.+ 74.28,22.7 75.55,23.96 77.45,23.96 79.36,22.06 R14.1
  Bottom 0.61: IC7.1 74.28,18.25 73.01,19.52 | C26.+ 74.28,20.79 73.01,19.52 | R6.2 73.01,19.52
N$20
  Bottom 0.406: K1.P1 85.71,62.7 86.98,61.43 C30.1 89.32,61.23 90.16,62.06 C29.1 R16.2
  Bottom 0.61: C29.1 93.13,61.86
N$21
  Bottom 0.61: T1.2 71.11,76.03 71.74,75.4 R5.2
N$22
  Top 0.406: U$1.16 71.16,34.07 71.74,33.49 | U$1.17 72.32,34.07 71.74,33.49 | C24.2 71.74,33.49
N$23
  Top 0.406: U$1.22 78.78,34.07 79.36,33.49 | U$1.23 79.94,34.07 79.36,33.49 | C25.2 79.36,33.49
N$24
  Bottom 0.61: K1.16 76.82,72.86 75.55,74.13 D5.A 75.55,76.67 74.28,77.94 T1.3
N$25
  Bottom 0.406: IC3.21 26.02,27.14 23.48,24.6 R3.1
N$26
  Top 0.406: C33.2 65.39,20.79 R7.2
  Bottom 0.406: IC7.3 73.01,11.9 67.93,16.98 R8.1 R7.2
N$27
  Bottom 0.61: IC7.7 85.08,14.44 88.89,18.25 R11.1 88.89,25.23 R15.1
N$28
  Bottom 0.61: IC7.6 R14.2 R11.2
N$29
  Bottom 0.406: R6.1 70.47,10.63 62.85,18.25 R9.2 64.12,20.79 69.2,20.79 69.2,18.25 73.01,14.44 IC7.2
N$30
  Bottom 0.813: R4.2 14.59,38.57 15.86,37.3 IC3.16
N$31
  Bottom 0.813: R4.1 LED5.A
N$32
  Bottom 0.406: R12.1 R13.2
N$33
  Bottom 0.406: IC7.5 92.06,9.36 95.87,13.17 R10.1 R12.2 92.7,40.48 89.52,43.65 87.62,43.65 C31.1 89.72,43.85 90.16,44.28 90.16,57.62 C30.2
N$34
  Bottom 0.61: R10.2 R16.1
N$40
  Bottom 0.406: X2.2 13.32,19.52 JP1.1
N$49
  Bottom 0.406: JP1.4 18.4,23.33 15.86,23.33 14.59,22.06 X2.3
N$50
  Bottom 0.406: JP1.3 20.94,18.25 20.94,14.44 19.67,13.17 18.4,13.17 17.13,14.44 IC4.8
N$51
  Bottom 0.406: IC4.7 19.67,16.98 18.4,18.25 18.4,20.79 JP1.2
N$52
  Bottom 0.305: IC4.4 C17.2
N$53
  Bottom 0.305: C17.1 24.75,16.98 IC4.5
N$56
  Bottom 0.406: IC4.3 C16.1
N$57
  Bottom 0.305: IC4.1 C16.2
N$58
  Bottom 0.406: C18.1 31.1,6.82 31.1,11.9 32.37,13.17 IC4.2
N$59
  Bottom 0.406: C19.1 23.48,6.82 23.48,11.9 22.21,13.17 IC4.6
N$250
  Bottom 1.016: D1.C 20.94,85.56 C3.1 22.21,89.37 29.83,89.37 32.37,91.91 C1.+ 41.26,91.91 42.53,90.64 42.53,86.83 46.34,83.02 D3.C 52.69,84.29 55.23,86.83 IC5.IN
OE\  (via drill 0.8, 0.8 pad 0.61)
  Top 0.305: v59.04,53.81 v55.23,53.81
  Bottom 0.305: IC1.24 62.85,39.84 62.85,46.19 61.58,47.46 61.58,51.27 v59.04,53.81 | v55.23,53.81 IC2.22
OFFS.  (via drill 0.8)
  Top 0.61: v45.07,14.44 48.88,10.63 59.04,10.63 60.31,9.36 R9.1
  Bottom 0.406: C15.+ 37.45,23.33 | 37.45,23.33 R3.2 | 37.45,23.33 41.26,23.33 42.53,22.06 42.53,16.98 v45.07,14.44
RES
  Bottom 0.305: IC3.29 33.64,47.46 37.45,43.65 37.45,38.57 39.99,36.03 39.99,34.76 41.26,33.49 43.8,33.49 IC1.3
RES\
  Bottom 0.305: C14.2 R1.1 4.43,62.7 5.7,63.97 8.24,63.97 | 8.24,63.97 PROG/SPI.5 | IC3.9 9.51,55.08 8.24,56.35 8.24,63.97
RUN
  Bottom 0.305: IC3.28 33.64,44.92 36.18,42.38 36.18,38.57 38.72,36.03 38.72,34.76 41.26,32.22 IC1.4
RXD
  Top 0.305: IC3.14 19.67,42.38 22.21,39.84 22.21,22.06 23.48,20.79 23.48,13.17 20.94,10.63 20.94,6.82 19.67,5.55 18.4,5.55 17.13,6.82 IC4.9
SCK
  Bottom 0.305: IC3.8 14.59,57.62 12.05,60.16 12.05,66.51 10.78,67.78 PROG/SPI.7
STO
  Bottom 0.305: IC3.27 33.64,42.38 34.91,41.11 34.91,38.57 37.45,36.03 37.45,34.76 41.26,30.95 43.8,30.95 IC1.8
TXD
  Top 0.305: IC4.10 19.67,10.63 20.94,11.9 20.94,38.57 19.67,39.84 IC3.15
VCC  (via drill 0.6)
  Top 0.305: IC1.21 59.04,33.49 L1.1 64.12,41.11 65.39,42.38 67.93,42.38 68.56,41.74 U$1.11 68.56,36.66 67.3,35.39 U$1.13
  Top 0.406: U$1.13 67.3,32.85 66.66,32.22 C20.2
  Top 1.016: 38.72,44.92 37.45,46.19 37.45,48.73 C9.2 39.99,53.81 IC2.28 | 38.72,44.92 42.53,44.92 IC1.41 47.61,39.84 52.69,39.84 | 52.69,39.84 IC1.32 | 52.69,39.84 52.69,36.03 56.5,32.22 IC1.21 | IC4.16 34.91,10.63 C10.2 39.99,15.71 | 38.72,44.92 37.45,43.65 37.45,27.14 C21.2 39.99,24.6 39.99,22.06 41.26,20.79 | D3.A 60.31,80.48 48.88,80.48 47.61,81.75 39.99,81.75 38.72,80.48 32.37,80.48 31.1,79.21 v23.48,79.21 | 41.26,20.79 PROG.1 | 41.26,20.79 39.99,19.52 39.99,15.71 | 39.99,15.71 QG1.14
  Bottom 0.61: C7.+ 78.85,77.18 80.63,75.4 80.63,66.51 79.36,65.24 K1.1 D5.C
  Bottom 1.016: C18.2 IC4.16 C11.2 | 23.48,52.54 26.02,50 IC3.30 C9.2 | 23.48,52.54 IC3.10 R1.2 9.51,52.54 6.97,55.08 PROG/SPI.2 | IC5.OUT D3.A C5.1 76.82,83.02 78.85,80.99 C7.+ | 23.48,52.54 v23.48,79.21
  other vias: 34.91,8.09
VCC/2  (via drill 0.6)
  Top 0.406: C23.2 74.28,32.22 73.65,32.85 U$1.18 73.65,35.39 73.01,36.03 70.47,36.03 69.84,35.39 U$1.15 69.2,33.49 | 69.2,33.49 U$1.14 | 69.2,33.49 C22.2 67.93,29.68 67.93,27.14 66.66,25.87 | 66.66,25.87 L1.2 62.85,24.6 62.85,21.42 61.58,20.15 61.58,15.71 R8.2 69.2,10.63 76.82,10.63 78.09,11.9 78.09,15.71 79.36,16.98 IC7.8 | 66.66,25.87 67.93,24.6 C32.+
  Bottom 0.406: IC7.8 C28.2 IC7.8
  other vias: 81.9,16.98
WE\
  Top 0.305: IC2.27 42.53,53.81 43.8,52.54 55.23,52.54 56.5,51.27 | 56.5,51.27 56.5,41.11 55.23,39.84 55.23,37.3 56.5,36.03 59.04,36.03 IC1.22 | 56.5,51.27 57.77,52.54 60.31,52.54 61.58,53.81 61.58,58.89 62.85,60.16 74.28,60.16 75.55,58.89 75.55,51.27 78.09,48.73 78.09,44.92 81.27,41.74 U$1.1

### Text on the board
Top: TOP
Bottom: BOT | www.ulrichradig.de
tNames: 40/50MSPS DSO | (C=) U. Radig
